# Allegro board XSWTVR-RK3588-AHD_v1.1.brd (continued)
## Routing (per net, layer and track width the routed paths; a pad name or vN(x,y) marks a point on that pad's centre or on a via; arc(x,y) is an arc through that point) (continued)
PCIE20_2_RXP/SATA30_2_RXP: length 140.1
  TOP w0.127: v1(107,100.68) 107.23,100.45 108.78,100.45 109.17,100.84 U1.186
  L3 w0.127: v1(107,100.68) 107.23,100.45 107.51,100.45 107.81,100.14 107.81,62.27 106.1,60.56 95.06,60.56 86.2,51.69 57.59,51.69 56.44,52.85 53.87,52.85 53.56,53.15 53.56,53.72 53.43,53.85 53.18,53.85 53.05,53.72 53.05,53.15 52.75,52.85 52.24,52.85 51.94,53.15 51.94,53.9 51.81,54.02 51.55,54.02 51.43,53.9 51.43,53.15 51.12,52.85 50.62,52.85 50.31,53.15 50.31,53.9 50.18,54.02 49.93,54.02 49.8,53.9 49.8,53.15 49.5,52.85 48.99,52.85 48.68,53.15 48.68,53.9 48.56,54.02 48.3,54.02 48.18,53.9 48.18,53.15 47.87,52.85 47.36,52.85 47.06,53.15 47.06,53.9 46.93,54.02 46.68,54.02 46.55,53.9 46.55,53.15 46.25,52.85 45.74,52.85 45.43,53.15 45.43,53.9 45.31,54.02 45.05,54.02 44.93,53.9 44.93,53.15 44.62,52.85 44.2,52.85 43.48,52.13 42.83,52.13 32.96,42.25 32.96,41.5 v1(33.18,41.28)
  BOTTOM w0.127: v1(33.18,41.28) 32.96,41.05 32.96,40.53 33.05,40.43 J2.43
PCIE20_2_TXN/SATA30_2_TXN: length 2.8
  TOP w0.127: C85.1 112.73,102.18 112.2,102.18 111.41,102.18 111.06,101.84 U1.187
PCIE20_2_TXP/SATA30_2_TXP: length 2.8
  TOP w0.127: U1.188 111.05,102.84 111.4,102.49 112.21,102.49 112.67,102.48 C86.1
PCIEX1_1_CLKREQN_M1_L: length 81.8
  TOP w0.127: v1(91.54,38.84) 91.54,39.19 92.63,40.29 101.65,40.29 101.89,40.05 J24.13
  L3 w0.127: v1(47.31,44.86) 48.39,43.78 48.39,39.91 52.43,35.86 72.28,35.86 73.91,37.5 84.59,37.5 85.95,38.86 91.44,38.86 91.46,38.84 v1(91.54,38.84)
  BOTTOM w0.127: J2.52 35.3,45.26 37.31,43.25 42.77,43.25 44.19,44.67 R53.1 44.69,44.22 46.67,44.22 v1(47.31,44.86)
PCIEX1_1_PERSTN_M1_L: length 83.9
  TOP w0.127: J24.11 102.89,39.6 101.84,40.64 92.32,40.64 90.89,39.22 90.89,38.51 v1(90.8,38.42)
  L3 w0.127: v1(47.33,44.17) 47.91,43.59 47.91,39.71 52.12,35.51 72.28,35.51 72.33,35.56 72.55,35.56 74.07,37.09 84.71,37.09 86.04,38.42 v1(90.8,38.42)
  BOTTOM w0.127: v1(47.33,44.17) 47.33,43.8 46.69,43.16 44.69,43.16 44.19,43.66 ; 44.19,43.66 43.84,43.66 43.1,42.91 36.99,42.91 34.8,45.09 J2.50 ; 44.19,43.66 R52.1
PCIEX1_1_WAKEN_M1_L: length 88
  TOP w0.127: v1(90.46,39.23) 90.46,39.64 91.83,41.01 102.02,41.01 103.41,39.63 103.41,35.9 103.58,35.72 105.26,35.72 105.39,35.6 J24.6
  L3 w0.127: v1(47.31,45.75) 48.85,44.22 48.85,40.04 52.67,36.21 72.17,36.21 73.79,37.83 84.46,37.83 85.86,39.23 90.46,39.23 v1(90.46,39.23)
  BOTTOM w0.127: R54.1 44.19,45.74 ; 44.19,45.74 44.69,45.23 46.79,45.23 v1(47.31,45.75) ; 44.19,45.74 44.19,45.7 43.56,45.07 43.56,44.56 42.56,43.57 37.66,43.57 35.8,45.42 J2.54
PHY0_CLKOUT125: length 4.1
  TOP w0.127: R155.2 130.42,86.57 130.42,87.51 129.72,88.2 U17.35
PHY0_LED0/CFG_EXT: length 8.7
  TOP w0.127: R158.2 132.98,82.03 R157.1 131.07,82.03 129.65,83.45 129.65,86.58 129.22,87.01 U17.32
PHY0_LED1/CFG_LDO0: length 6.3
  TOP w0.127: U17.33 129.41,87.4 129.91,86.9 129.91,84.04 R161.1
PHY0_LED2/CFG_LDO1: length 8.5
  TOP w0.127: R160.2 132.72,84.54 131.54,84.54 R159.1 130.16,84.79 130.16,87.24 129.59,87.81 U17.34
PHY0_MDI0+: length 18
  TOP w0.127: U17.1 127.58,90.85 127.58,91.35 127.79,91.56 129.03,91.56 129.5,92.03 129.5,92.71 v1(129.72,92.93) ; R137.1 120.02,94.52 120.02,94.22 v1(119.79,93.99)
  BOTTOM w0.127: v1(129.72,92.93) 129.5,93.15 129.5,94.76 128.51,95.75 120.97,95.75 120.02,94.8 120.02,94.22 v1(119.79,93.99)
PHY0_MDI0-: length 17.9
  TOP w0.127: R138.1 120.32,94.52 120.32,94.22 v1(120.55,93.99) ; U17.2 127.27,90.85 127.27,91.47 127.66,91.86 128.9,91.86 129.19,92.15 129.19,92.71 v1(128.97,92.93)
  BOTTOM w0.127: v1(128.97,92.93) 129.2,93.17 129.2,93.42 129.07,93.55 128.91,93.55 128.78,93.68 128.78,93.93 128.91,94.06 129.07,94.06 129.2,94.18 129.2,94.63 128.39,95.44 123.1,95.44 122.98,95.32 122.98,95.24 122.85,95.11 122.6,95.11 122.47,95.24 122.47,95.32 122.34,95.44 121.09,95.44 120.32,94.67 120.32,94.22 v1(120.55,93.99)
PHY0_MDI1+: length 8.6
  TOP w0.127: U17.4 126.38,90.85 126.38,93.83 v1(126.6,94.05) ; v1(123.56,94.03) 123.8,94.27 123.8,94.56 R141.1
  BOTTOM w0.127: v1(126.6,94.05) 126.38,94.28 126.38,94.59 126.06,94.9 124.1,94.9 123.79,94.59 123.79,94.26 v1(123.56,94.03)
PHY0_MDI1-: length 8.5
  TOP w0.127: R142.1 124.1,94.56 124.1,94.24 v1(124.31,94.03) ; U17.5 126.07,90.85 126.07,92.81 125.94,92.94 125.69,92.94 125.56,93.07 125.56,93.32 125.69,93.45 125.94,93.45 126.07,93.57 126.07,93.83 v1(125.84,94.05)
  BOTTOM w0.127: v1(125.84,94.05) 126.07,94.28 126.07,94.46 125.94,94.59 125.45,94.59 125.32,94.47 125.32,94.44 125.2,94.31 124.94,94.31 124.82,94.44 124.82,94.47 124.69,94.59 124.23,94.59 124.09,94.46 124.09,94.24 v1(124.31,94.03)
PHY0_MDI2+: length 9.5
  TOP w0.127: v1(125,93.41) 124.77,93.18 124.77,92.59 125.57,91.79 125.57,90.85 U17.6 ; v1(127.39,94.05) 127.62,94.28 127.62,94.54 R143.1
  BOTTOM w0.127: v1(127.39,94.05) 127.64,93.8 127.64,93.15 127.41,92.93 127.16,92.93 127.03,93.06 127.03,93.16 126.87,93.33 126.69,93.33 126.53,93.16 126.53,93.06 126.4,92.93 126.14,92.93 126.02,93.06 126.02,93.16 125.89,93.29 125.64,93.29 125.51,93.16 125.51,93.06 125.38,92.93 124.9,92.93 124.77,93.06 124.77,93.2 124.98,93.41 v1(125,93.41)
PHY0_MDI2-: length 9.6
  TOP w0.127: R145.1 127.92,94.54 127.92,94.28 v1(128.15,94.05) ; U17.7 125.27,90.85 125.27,91.66 124.47,92.46 124.47,93.18 v1(124.24,93.41)
  BOTTOM w0.127: v1(124.24,93.41) 124.47,93.18 124.47,92.93 124.77,92.62 127.54,92.62 127.94,93.02 127.94,93.84 v1(128.15,94.05)
PHY0_MDI3+: length 17.2
  TOP w0.127: R146.1 131.43,94.54 131.43,94.29 v1(131.2,94.06) ; v1(122.62,92.83) 122.39,92.61 122.39,92.05 122.63,91.81 124.02,91.81 124.37,91.45 124.37,90.86 U17.9
  BOTTOM w0.127: v1(122.62,92.83) 122.36,92.58 122.36,92.32 122.57,92.11 123.3,92.11 123.43,92.24 123.43,92.29 123.55,92.42 123.81,92.42 123.93,92.29 123.93,92.24 124.06,92.11 127.76,92.11 127.99,92.34 128.27,92.34 128.5,92.11 128.78,92.11 129,92.34 129.29,92.34 129.51,92.11 129.79,92.11 130.02,92.34 130.3,92.34 130.53,92.11 130.78,92.11 131.43,92.76 131.43,93.84 v1(131.2,94.06)
PHY0_MDI3-: length 17.3
  TOP w0.127: U17.10 124.07,90.85 124.07,91.33 123.89,91.5 122.5,91.5 122.08,91.92 122.08,92.61 v1(121.86,92.83) ; v1(131.96,94.06) 131.73,94.29 131.73,94.54 R147.1
  BOTTOM w0.127: v1(131.96,94.06) 131.73,93.84 131.73,92.63 130.91,91.81 122.44,91.81 122.06,92.19 122.06,92.63 v1(121.86,92.83)
PHY0_MDI_0+: length 2.4
  TOP w0.127: R137.2 120.02,96.28 120.02,96.88 119.54,97.36 U16.2
PHY0_MDI_0-: length 2.4
  TOP w0.127: U16.3 120.81,97.37 120.33,96.89 120.33,96.28 R138.2
PHY0_MDI_1+: length 2.4
  TOP w0.127: R141.2 123.84,96.27 123.84,96.85 123.35,97.33 U16.5
PHY0_MDI_1-: length 2.4
  TOP w0.127: R142.2 124.14,96.19 124.14,96.89 124.62,97.37 U16.6
PHY0_MDI_2+: length 2.4
  TOP w0.127: U16.8 127.17,97.36 127.66,96.88 127.66,96.29 R143.2
PHY0_MDI_2-: length 2.4
  TOP w0.127: R145.2 127.96,96.21 127.96,96.93 128.44,97.41 U16.9
PHY0_MDI_3+: length 2.4
  TOP w0.127: R146.2 131.46,96.29 131.46,96.88 130.98,97.36 U16.11
PHY0_MDI_3-: length 2.4
  TOP w0.127: U16.12 132.25,97.35 131.77,96.87 131.77,96.21 R147.2
PHY0_RSTN: length 4.8
  TOP w0.127: U17.12 121.92,89.81 121.31,90.42 R177.2 R175.2 120.87,92.37 C278.1
PHY0_RXCLK/PHYAD1: length 5
  TOP w0.127: U17.27 126.42,84.13 R165.1 125.72,83.43 125.72,82.01 R182.1
PHY0_RXD0/RXDLY: length 8.4
  TOP w0.127: R178.1 124.08,79.3 123.63,79.75 123.63,80.99 R168.1 123.63,82 123.63,83.43 R169.2 124.59,84.39 124.94,84.39 125.62,85.07 U17.25
PHY0_RXD1/TXDLY: length 9
  TOP w0.127: U17.24 125.22,85.27 124.66,84.7 123.85,84.7 R171.2 122.57,83.43 122.57,82 R170.1 122.54,80.95 122.54,79.79 123.03,79.3 R179.1
PHY0_RXD2/PLLOFF: length 9.5
  TOP w0.127: U17.23 124.82,85.42 124.38,84.98 123.08,84.98 R174.2 121.49,83.4 121.49,82.02 R173.1 121.5,80.97 121.5,79.78 121.97,79.3 R180.1
PHY0_RXD3/PHYAD0: length 10.1
  TOP w0.127: R181.1 120.92,79.3 120.42,79.8 120.42,80.94 R163.1 120.45,82.01 120.45,83.41 R164.2 122.28,85.24 124.09,85.24 124.42,85.57 U17.22
PHY0_RXDV/PHYAD2: length 5.3
  TOP w0.127: R183.1 124.67,82.01 124.67,83.43 R166.1 126.02,84.79 U17.26
PHY0_XTALIN: length 7.8
  TOP w0.203: Y3.3 134.02,88.62 132.41,88.62 C259.1 131.53,88.53 131.24,88.53 R140.1 130.51,88.61 U17.36
PHY0_XTALOUT: length 6.4
  TOP w0.203: U17.37 130.6,89.01 R148.2 131.25,88.98 131.54,88.98 C258.1 132.35,88.95 132.95,88.95 133.29,89.29 Y3.1
PHY1_CLKOUT125: length 4
  TOP w0.127: U19.35 151.62,88.27 152.45,87.44 152.45,86.64 R198.2
PHY1_LED0/CFG_EXT: length 8.7
  TOP w0.127: U19.32 151.13,87.07 151.67,86.54 151.67,83.57 152.64,82.6 153.45,82.6 R200.1 153.94,82.1 R201.2
PHY1_LED1/CFG_LDO0: length 6.1
  TOP w0.127: R204.1 151.94,84.12 151.94,86.81 151.28,87.47 U19.33
PHY1_LED2/CFG_LDO1: length 8.2
  TOP w0.127: U19.34 151.44,87.87 152.2,87.11 152.2,84.87 R202.1 153.48,84.66 154.59,84.66 R203.2
PHY1_MDI0+: length 18.1
  TOP w0.127: R185.1 141.91,94.56 141.91,94.26 v1(141.68,94.04) ; v1(151.75,93) 151.53,92.78 151.53,92.16 151.11,91.74 149.78,91.74 149.61,91.56 149.61,91.17 149.66,91.12 U19.1
  BOTTOM w0.127: v1(151.75,93) 151.52,93.23 151.52,94.71 150.44,95.79 142.86,95.79 141.91,94.84 141.91,94.26 v1(141.68,94.04)
PHY1_MDI0-: length 18
  TOP w0.127: v1(142.44,94.04) 142.23,94.25 142.23,94.58 R184.1 ; v1(151,93) 151.22,92.78 151.22,92.28 150.98,92.04 149.66,92.04 149.3,91.69 149.3,91.15 149.26,91.11 U19.2
  BOTTOM w0.127: v1(151,93) 151.22,93.22 151.22,94.58 150.32,95.49 145.02,95.49 144.89,95.36 144.89,95.23 144.76,95.11 144.51,95.11 144.38,95.23 144.38,95.36 144.25,95.49 144,95.49 143.87,95.36 143.87,95.23 143.75,95.11 143.49,95.11 143.36,95.23 143.36,95.36 143.24,95.49 142.98,95.49 142.21,94.72 142.21,94.26 v1(142.44,94.04)
PHY1_MDI1+: length 8.7
  TOP w0.127: v1(148.63,94.12) 148.41,93.9 148.41,91.18 148.46,91.13 U19.4 ; R187.1 145.69,94.61 145.69,94.32 v1(145.45,94.08)
  BOTTOM w0.127: v1(145.45,94.08) 145.66,94.29 145.66,94.64 146.07,95.04 147.79,95.04 148.38,94.46 148.38,94.33 148.58,94.12 v1(148.63,94.12)
PHY1_MDI1-: length 8.6
  TOP w0.127: R188.1 145.99,94.61 145.99,94.29 v1(146.2,94.08) ; U19.5 148.06,91.11 148.1,91.15 148.1,92.63 147.98,92.76 147.57,92.76 147.45,92.89 147.45,93.14 147.57,93.27 147.98,93.27 148.1,93.4 148.1,93.9 v1(147.88,94.12)
  BOTTOM w0.127: v1(147.88,94.12) 147.99,94.23 147.99,94.41 147.67,94.74 146.19,94.74 145.97,94.51 145.97,94.32 v1(146.2,94.08)
PHY1_MDI2+: length 9.3
  TOP w0.127: v1(149.28,94.1) 149.51,94.33 149.51,94.59 R189.1 ; U19.6 147.66,91.39 147.61,91.44 147.61,91.88 146.81,92.68 146.81,93.3 v1(147.04,93.54)
  BOTTOM w0.127: v1(149.28,94.1) 149.53,93.85 149.53,93.22 149.4,93.09 148.8,93.09 148.69,93.2 148.69,93.33 148.58,93.44 148.42,93.44 148.31,93.33 148.31,93.2 148.2,93.09 148.04,93.09 147.93,93.2 147.93,93.33 147.82,93.44 147.66,93.44 147.55,93.33 147.55,93.2 147.43,93.09 146.93,93.09 146.8,93.22 146.8,93.3 v1(147.04,93.54)
PHY1_MDI2-: length 9.4
  TOP w0.127: U19.7 147.26,91.39 147.3,91.44 147.3,91.76 146.5,92.56 146.5,93.33 v1(146.29,93.54) ; R190.1 149.81,94.59 149.81,94.33 v1(150.04,94.1)
  BOTTOM w0.127: v1(146.29,93.54) 146.49,93.33 146.49,93.09 146.8,92.78 149.53,92.78 149.83,93.09 149.83,93.9 v1(150.04,94.1)
PHY1_MDI3+: length 16.3
  TOP w0.127: U19.9 146.41,90.92 146.41,91.52 146.05,91.87 144.67,91.87 144.42,92.12 144.42,92.68 v1(144.65,92.9) ; v1(153.09,94.12) 153.32,94.34 153.32,94.59 R191.1
  BOTTOM w0.127: v1(153.09,94.12) 153.31,93.89 153.31,93.28 152.49,92.46 145.86,92.46 145.73,92.58 145.73,92.97 145.61,93.1 145.35,93.1 145.22,92.97 145.22,92.58 145.1,92.46 144.64,92.46 144.51,92.58 144.51,92.76 v1(144.65,92.9)
PHY1_MDI3-: length 16.4
  TOP w0.127: v1(143.89,92.9) 144.12,92.68 144.12,92 144.54,91.57 145.93,91.57 146.1,91.39 146.1,90.92 U19.10 ; R192.1 153.62,94.59 153.62,94.34 v1(153.85,94.12)
  BOTTOM w0.127: v1(143.89,92.9) 144.2,92.59 144.2,92.46 144.51,92.15 152.61,92.15 153.62,93.16 153.62,93.89 v1(153.85,94.12)
PHY1_MDI_0+: length 2.4
  TOP w0.127: R185.2 141.92,96.33 141.92,96.92 141.43,97.4 U18.2
PHY1_MDI_0-: length 2.4
  TOP w0.127: U18.3 142.7,97.4 142.22,96.92 142.22,96.32 R184.2
PHY1_MDI_1+: length 2.4
  TOP w0.127: R187.2 145.73,96.32 145.73,96.89 145.24,97.38 U18.5
PHY1_MDI_1-: length 2.4
  TOP w0.127: U18.6 146.51,97.41 146.03,96.93 146.03,96.25 R188.2
PHY1_MDI_2+: length 2.4
  TOP w0.127: U18.8 149.06,97.38 149.52,96.93 149.52,96.31 R189.2
PHY1_MDI_2-: length 2.4
  TOP w0.127: R190.2 149.82,96.29 149.82,96.91 150.33,97.42 U18.9
PHY1_MDI_3+: length 2.4
  TOP w0.127: U18.11 152.87,97.39 153.34,96.92 153.34,96.32 R191.2
PHY1_MDI_3-: length 2.4
  TOP w0.127: R192.2 153.64,96.28 153.64,96.89 154.14,97.39 U18.12
PHY1_RSTN: length 4.7
  TOP w0.127: C300.1 143.03,92.45 R219.2 R221.2 143.15,90.48 143.76,89.87 U19.12
PHY1_RXCLK/PHYAD1: length 5
  TOP w0.127: R226.1 147.83,82.1 147.83,83.52 R209.1 148.46,84.14 U19.27
PHY1_RXD0/RXDLY: length 8.6
  TOP w0.127: U19.25 147.66,85 147.13,84.48 146.71,84.48 R213.2 145.74,83.52 145.74,82.08 R212.1 145.75,81.08 145.75,79.61 R222.1
PHY1_RXD1/TXDLY: length 9.2
  TOP w0.127: U19.24 147.26,85.18 146.82,84.73 146.6,84.73 145.91,84.73 R215.2 144.66,83.49 144.66,82.11 R214.1 144.68,81.06 144.68,79.63 R223.1
PHY1_RXD2/PLLOFF: length 9.8
  TOP w0.127: U19.23 146.86,85.31 146.54,84.99 145.11,84.99 R218.2 143.61,83.49 143.61,82.11 R217.1 143.63,81.07 143.63,79.62 R224.1
PHY1_RXD3/PHYAD0: length 10.3
  TOP w0.127: R225.1 142.58,79.62 142.58,81.08 R207.1 142.59,82.07 142.59,83.53 R208.2 144.34,85.27 146.27,85.27 146.46,85.47 U19.22
PHY1_RXDV/PHYAD2: length 5.3
  TOP w0.127: U19.26 148.06,84.79 R210.1 146.76,83.5 146.76,82.12 R227.1
PHY1_XTALIN: length 7.8
  TOP w0.203: U19.36 152.54,88.67 R186.1 153.26,88.59 153.6,88.59 153.96,88.23 C284.1 154.44,88.68 156.07,88.68 Y4.3
PHY1_XTALOUT: length 6.4
  TOP w0.203: U19.37 152.63,89.07 R193.2 153.28,89.05 153.57,89.05 C283.1 154.39,89.02 155,89.02 155.33,89.35 Y4.1
POWER_EN: length 88
  TOP w0.127: U8.21 106.17,31.08 107.62,32.52 112.92,32.52 v1(113.18,32.26)
  TOP w0.203: U2.3 146.37,70.89 v1(147.12,71.65) R6.2
  BOTTOM w0.127: v1(147.12,71.65) 147.12,72.43 145.54,74.01 131.64,74.01 127.96,70.32 114.08,70.32 113.67,69.91 113.67,62.93 113.18,62.43 113.18,32.78 113.18,32.78 v1(113.18,32.26)
RESET_L: length 98.9
  TOP w0.127: v1(30.35,123.95) ED28.1 29.78,124.8 28.85,125.74 28.85,129.75 U24.J2 ; v1(40.56,62.65) 40.56,50.3 41.97,48.88 R2.2
  BOTTOM w0.127: v1(30.35,123.95) 30.35,123.55 33.36,120.55 39.11,120.55 41.91,117.75 41.91,95.73 45.27,92.37 45.27,67.37 v1(40.56,62.65)
RFFE_VIO_1V8: length 26.9
  BOTTOM w0.127: R344.1 26.7,31.8 C376.1 25.81,32.81 25.81,37.67 26.63,38.49 26.63,41.05 27.52,41.94 37.7,41.94 38.55,41.09 J2.65 ; R344.1 26.24,30.84 26.24,30.84 R51.2 ; R344.1 26.69,30.83 R68.1
RM500U_RESET: length 21.3
  BOTTOM w0.127: Q1.3 24.25,36.86 C84.2 26.19,38.8 26.19,41.2 27.29,42.3 37.94,42.3 39.05,41.19 J2.67
RS232_RXD: length 168.9
  TOP w0.127: v1(18.45,123.93) ED21.1 17.83,125.17 17.28,125.72 17.28,135.62 U24.M3 ; R307.2 89.75,17.48 89.91,17.65 90.24,17.65 v1(90.3,17.71)
  BOTTOM w0.127: v1(18.45,123.93) 19.29,123.09 19.29,121.69 35,105.98 35,105.98 36.31,104.67 36.31,62.88 44.24,54.95 51.94,54.95 59.49,47.41 59.49,29.55 62.73,26.31 62.73,24.28 65.94,21.07 85.22,21.07 88.58,17.71 v1(90.3,17.71)
RS232_TXD: length 171.7
  TOP w0.127: v1(90.27,18.37) 90.26,18.37 90.07,18.18 R306.2 ; v1(19.66,123.93) ED22.1 19.09,125.17 17.93,126.34 17.93,137.77 15.62,140.08 U24.M4
  BOTTOM w0.127: v1(19.66,123.93) 20.16,123.42 20.16,121.3 36.7,104.76 36.7,62.93 44.37,55.26 52.14,55.26 59.83,47.56 59.83,29.77 63.07,26.53 63.07,24.46 66.16,21.38 85.45,21.38 88.46,18.37 v1(90.27,18.37)
RSET0: length 3.5
  TOP w0.127: U17.39 129.01,89.81 R162.1
RSET1: length 3.4
  TOP w0.127: R205.1 151.07,89.87 U19.39
RTC_IN: length 6
  TOP w0.203: U8.3 111.44,21.03 111.66,20.81 111.66,20.05 112.13,19.58 112.41,19.58 C60.1 114.13,19.08 X1.1
RTC_OUT: length 6
  TOP w0.203: U8.4 111.53,21.53 112.03,21.03 112.03,20.24 112.23,20.04 112.53,20.04 C61.1 114.13,20.41 X1.2
RUN_LED: length 197.4
  TOP w0.127: v1(92.48,26.11) 94.32,26.11 95.01,25.41 95.01,23.57 97.05,21.53 U8.45 ; 55.95,109.56 54.27,109.56 v1(53.88,109.18)
  TOP w0.203: D41.4 60.3,152.67 57.66,150.02 57.66,125.85 58.01,125.49 58.01,116.96 58.17,116.8 58.17,111.79 55.95,109.56
  BOTTOM w0.127: v1(53.88,109.18) 51.57,106.86 49.88,106.86 48.91,105.9 48.91,61.12 49.37,60.66 56.38,60.66 58.28,58.76 71.21,58.76 72.72,57.24 72.72,42.41 73.42,41.71 76.13,41.71 76.32,41.52 97.36,41.52 100.67,38.21 100.67,35.62 98.94,33.89 96.36,33.89 92.48,30.02 v1(92.48,26.11)
SARADC_VIN1_KEY/RECOVERY: length 11
  TOP w0.127: U1.1 44.1,106.84 40.74,103.48 37.4,103.48 R1.1 36.81,102.93 ED1.2
SATA0_RXN: length 4.4
  BOTTOM w0.127: U21.43 151.23,56.55 151.22,56.53 151.86,56.53 151.96,56.44 152.68,56.44 152.98,56.74 154.52,56.74 154.71,56.93 154.91,56.93 C357.2
SATA0_RXP: length 4.3
  BOTTOM w0.127: C358.2 154.84,56.63 154.65,56.43 153.1,56.43 152.8,56.13 151.95,56.13 151.85,56.03 151.22,56.03 151.23,56.05 U21.41
SATA0_TXN: length 2.3
  BOTTOM w0.127: C355.2 153.34,57.63 151.99,57.63 151.89,57.53 151.23,57.53 U21.47
SATA0_TXP: length 2.4
  BOTTOM w0.127: U21.49 151.23,58.03 151.92,58.03 152.02,57.94 153.3,57.94 C356.2
SCL_CODEC: length 21.7
  TOP w0.127: R265.1 v1(53.87,117.87) ; v1(57.22,116.39) 57.55,116.06 57.55,112.04 55.62,110.11 48.46,110.11 47.31,108.95 U1.255
  BOTTOM w0.127: v1(57.22,116.39) 55.75,117.87 v1(53.87,117.87)
SD_CLK: length 56.7
  TOP w0.127: R128.1 v1(60.3,138.96) ; U1.11 v1(46.61,96.84)
  L3 w0.127: v1(60.3,138.96) 58.33,136.99 58.33,124.01 59.85,122.5 59.85,121.74 v1(59.25,121.14)
  BOTTOM w0.127: v1(59.25,121.14) 59.99,121.14 61.26,119.87 61.26,113.15 57.95,109.84 51.97,109.84 48.61,106.48 48.61,98.83 v1(46.61,96.84)
SDA_CODEC: length 21
  TOP w0.127: U1.256 46.31,107.93 46.31,108.56 48.1,110.36 49.71,110.36 49.71,110.36 55.42,110.36 57.28,112.22 57.28,115.46 v1(56.94,115.79) ; R266.1 v1(53.87,116.88)
  BOTTOM w0.127: v1(56.94,115.79) 56.89,115.79 55.8,116.88 v1(53.87,116.88)
SDMMC0_CMD: length 56.2
  TOP w0.127: U1.10 v1(46.6,97.84) ; R127.1 v1(60.29,139.99)
  L3 w0.127: v1(60.29,139.99) 57.71,137.41 57.71,123.7 v1(59.24,122.17)
  BOTTOM w0.127: v1(46.6,97.84) 48.07,99.31 48.07,106.83 51.57,110.33 57.52,110.33 60.7,113.51 60.7,119.22 59.22,120.7 59.09,120.7 58.85,120.93 58.85,121.78 v1(59.24,122.17)
SDMMC0_D0: length 55.4
  TOP w0.127: v1(46.57,101.84) 46.45,101.84 U1.6 ; R123.1 v1(60.32,135.84)
  L3 w0.127: v1(59.24,118.03) 59.6,118.03 61.71,120.14 61.71,123.22 60.59,124.35 60.59,124.6 60.46,124.73 60.14,124.73 60.01,124.85 60.01,125.11 60.14,125.24 60.46,125.24 60.59,125.36 60.59,125.62 60.46,125.74 60.14,125.74 60.01,125.87 60.01,126.12 60.14,126.25 60.46,126.25 60.59,126.38 60.59,126.63 60.46,126.76 60.14,126.76 60.01,126.89 60.01,127.14 60.14,127.27 60.46,127.27 60.59,127.39 60.59,127.65 60.46,127.78 60.14,127.78 60.01,127.9 60.01,128.16 60.14,128.28 60.46,128.28 60.59,128.41 60.59,128.66 60.46,128.79 60.14,128.79 60.01,128.92 60.01,129.17 60.14,129.3 60.46,129.3 60.59,129.43 60.59,129.68 60.46,129.81 60.14,129.81 60.01,129.93 60.01,130.19 60.14,130.32 60.46,130.32 60.59,130.44 60.59,131.38 60.46,131.51 60.07,131.51 59.95,131.64 59.95,131.89 60.07,132.02 60.46,132.02 60.59,132.14 60.59,132.4 60.46,132.52 60.07,132.52 59.95,132.65 59.95,132.91 60.07,133.03 60.46,133.03 60.59,133.16 60.59,133.41 59.96,134.04 59.96,135.48 v1(60.32,135.84)
  BOTTOM w0.127: v1(46.57,101.84) 46.21,102.2 46.21,109.04 48.76,111.6 55.41,111.6 55.41,111.61 56.7,111.61 58.74,113.65 58.74,117.54 v1(59.24,118.03)
SDMMC0_D1: length 55.8
  TOP w0.127: U1.7 46.42,100.84 46.46,100.8 v1(46.57,100.8) ; R124.1 v1(60.33,134.81)
  L3 w0.127: v1(60.33,134.81) 61.25,133.89 61.25,129.87 61.38,129.74 61.84,129.74 61.97,129.61 61.97,129.36 61.84,129.23 61.38,129.23 61.25,129.11 61.25,128.85 61.38,128.73 61.84,128.73 61.97,128.6 61.97,128.34 61.84,128.22 61.38,128.22 61.25,128.09 61.25,127.84 61.38,127.71 61.84,127.71 61.97,127.58 61.97,127.33 61.84,127.2 61.38,127.2 61.25,127.07 61.25,126.82 61.38,126.69 61.84,126.69 61.97,126.57 61.97,126.31 61.84,126.19 61.38,126.19 61.25,126.06 61.25,125.8 61.38,125.68 61.84,125.68 61.97,125.55 61.97,125.3 61.84,125.17 61.38,125.17 61.25,125.04 61.25,124.65 62.17,123.73 62.17,119.93 v1(59.24,116.99)
  BOTTOM w0.127: v1(46.57,100.8) 46.7,100.93 46.7,101.36 46.98,101.64 46.98,102.14 46.7,102.42 46.7,102.98 46.97,103.25 46.97,103.49 46.7,103.76 46.7,104 46.97,104.27 46.97,104.51 46.7,104.78 46.7,105.02 46.97,105.29 46.97,105.52 46.56,105.93 46.56,108.66 46.87,108.97 47.05,108.97 47.13,108.88 47.31,108.88 47.49,109.06 47.49,109.24 47.41,109.33 47.41,109.51 47.59,109.69 47.77,109.69 47.85,109.6 48.03,109.6 48.21,109.78 48.21,109.96 48.13,110.05 48.13,110.22 48.31,110.4 48.49,110.4 48.57,110.32 48.75,110.32 48.93,110.5 48.93,110.68 48.84,110.76 48.84,110.94 49.18,111.28 56.88,111.28 59.24,113.64 v1(59.24,116.99)
SDMMC0_D2: length 55.2
  TOP w0.127: U1.8 46.52,99.84 v1(46.57,99.84) ; R125.1 v1(60.32,136.88)
  L3 w0.127: v1(60.32,136.88) 59.6,136.16 59.6,133.73 59.55,133.68 59.55,133.13 59.39,132.97 59.39,132.62 59.54,132.46 59.54,132.11 59.39,131.95 59.39,131.6 59.54,131.45 59.54,131.09 59.39,130.94 59.39,130.58 59.54,130.43 59.54,130.08 59.39,129.92 59.39,129.57 59.54,129.41 59.54,129.06 59.39,128.91 59.39,128.55 59.54,128.4 59.54,128.04 59.39,127.89 59.39,127.54 59.54,127.38 59.54,127.03 59.39,126.87 59.39,126.52 59.54,126.37 59.54,126.01 59.39,125.86 59.39,125.5 59.54,125.35 59.54,124.7 61.06,123.18 61.06,122.93 61.27,122.72 61.27,122.42 61.17,122.31 60.96,122.31 60.86,122.21 60.86,121.91 60.96,121.81 61.17,121.81 61.27,121.7 61.27,121.4 61.06,121.2 61.06,120.89 60.75,120.58 60.75,120.4 60.95,120.2 60.95,120.02 60.77,119.84 60.59,119.84 60.39,120.04 60.21,120.04 60.04,119.86 60.04,119.68 60.23,119.48 60.23,119.3 60.05,119.12 59.88,119.12 59.68,119.32 59.5,119.32 v1(59.24,119.06)
  BOTTOM w0.127: v1(46.57,99.84) 47.35,100.62 47.35,105.97 47.16,106.16 47.08,106.16 46.95,106.29 46.95,106.55 47.08,106.67 47.16,106.67 47.28,106.8 47.28,107.05 47.16,107.18 47.08,107.18 46.95,107.31 46.95,107.56 47.08,107.69 47.16,107.69 47.28,107.82 47.28,108.13 50.1,110.95 57.07,110.95 59.66,113.54 59.66,114.61 59.87,114.83 59.87,115.12 59.66,115.34 59.66,115.63 59.87,115.85 59.87,116.14 59.66,116.35 59.66,116.65 59.87,116.86 59.87,117.15 59.66,117.37 59.66,117.66 59.87,117.88 59.87,118.17 59.66,118.39 59.66,118.64 v1(59.24,119.06)
SDMMC0_D3: length 54.9
  TOP w0.127: U1.9 v1(46.57,98.84) ; R126.1 v1(60.31,137.91)
  L3 w0.127: v1(60.31,137.91) 58.88,136.48 58.88,124.36 60.4,122.84 60.4,121.25 v1(59.24,120.09)
  BOTTOM w0.127: v1(46.57,98.84) 47.74,100 47.74,107.15 48.32,107.73 48.32,107.91 48.1,108.13 48.1,108.31 48.28,108.48 48.46,108.48 48.68,108.27 48.86,108.27 49.04,108.45 49.04,108.63 48.82,108.84 48.82,109.02 49,109.2 49.18,109.2 49.39,108.99 49.57,108.99 49.75,109.16 49.75,109.34 49.54,109.56 49.54,109.74 49.72,109.92 49.89,109.92 50.11,109.7 50.29,109.7 51.23,110.64 57.28,110.64 60.28,113.63 60.28,119.05 v1(59.24,120.09)
SDMMC_CLK: length 11.8
  TOP w0.127: R359.1 21.4,26.12 25.18,22.34 27,22.34 27.75,23.08 U22.18
SDMMC_CMD: length 14.2
  TOP w0.127: R254.1 22.51,23.99 24.81,21.7 27.35,21.7 29.15,23.49 29.15,26.85 28.93,27.07 U22.20
SDMMC_D0: length 5.8
  TOP w0.127: U22.13 22.61,25.91 20.84,27.67 R255.1
SDMMC_D1: length 5.8
  TOP w0.127: U22.12 22.76,26.57 21.55,27.78 21.55,29.19 21.29,29.46 R256.1
SDMMC_D2: length 18.4
  TOP w0.127: R252.1 22.89,21.8 24.18,20.51 27.91,20.51 30.4,23 30.4,28.03 29.86,28.57 U22.23
SDMMC_D3: length 16.4
  TOP w0.127: U22.22 29.24,28.07 29.77,27.54 29.77,23.31 27.59,21.13 24.46,21.13 22.69,22.9 R253.1
SDMMC_DET_L: length 15.9
  TOP w0.127: J22.9 17.46,30.59 D26.1 17.51,30.59 19.04,32.13 22.15,32.13 22.42,31.86 22.42,29.21 24.06,27.57 U22.10
SWCLK: length 9.4
  TOP w0.127: U8.49 100.67,18.84 100.32,19.19 97,19.19 J1.2
SWDIO: length 7.1
  TOP w0.127: J1.3 93.64,24.33 96.93,21.03 U8.46
TYPEC0_OTG_DM: length 25.4
  TOP w0.127: U1.58 44.52,49.84 44.17,50.19 43.34,50.19 41.48,52.04 41.48,64.79 39.83,66.44 34.98,66.44 R228.2
TYPEC0_OTG_DP: length 25.4
  TOP w0.127: R230.2 34.98,66.72 39.95,66.72 41.76,64.9 41.76,52.16 43.45,50.47 44.16,50.47 44.53,50.84 U1.57
TYPEC0_SSRX1N: length 24.2
  TOP w0.127: U1.66 47.31,42.6 46.15,41.44 42.52,41.44 36.42,47.54 36.42,49.37 33.32,52.48 29.97,52.48 R233.1
TYPEC0_SSRX1P: length 24.1
  TOP w0.127: U1.65 46.31,42 46.03,41.72 42.64,41.72 42.36,42 42.36,42.3 42.15,42.51 41.85,42.51 41.64,42.71 41.64,43.01 41.43,43.22 41.13,43.22 40.92,43.43 40.92,43.73 40.71,43.94 40.41,43.94 40.2,44.15 40.2,44.45 39.99,44.66 39.69,44.66 36.7,47.65 36.7,49.49 33.43,52.76 29.99,52.76 R234.1
TYPEC0_SSTX1N: length 28.8
  TOP w0.127: C309.1 29.85,50.09 34.43,50.09 35.19,49.32 35.19,46.67 41.46,40.4 49.82,40.4 50.6,41.17 50.6,41.5 51.31,42.21 U1.70
TYPEC0_SSTX1P: length 28.8
  TOP w0.127: C313.1 29.66,50.54 29.83,50.37 30.86,50.37 30.98,50.49 30.98,50.51 31.11,50.63 31.36,50.63 31.49,50.51 31.49,50.49 31.62,50.37 31.87,50.37 32,50.49 32,50.51 32.13,50.63 32.38,50.63 32.51,50.51 32.51,50.49 32.63,50.37 32.89,50.37 33.01,50.49 33.01,50.51 33.14,50.63 33.4,50.63 33.52,50.51 33.52,50.49 33.65,50.37 34.55,50.37 35.47,49.44 35.47,46.78 41.58,40.68 49.71,40.68 50.31,41.28 U1.69
TYPEC0_USB20_OTG_ID: length 16.2
  TOP w0.127: SW3.2 56.78,117.31 57.29,116.79 57.55,116.79 57.81,116.53 57.81,111.91 55.72,109.82 50.96,109.82 50.31,109.17 U1.252
TYPEC0_USB20_VBUSDET: length 21.8
  TOP w0.127: R236.2 R238.1 C314.1 39.91,62.1 39.91,59.25 39.56,58.91 39.56,49.77 41.49,47.84 U1.60
UART1_RX_M1: length 81.7
  TOP w0.127: U1.240 v1(62.31,109.15)
  L3 w0.127: v1(62.31,109.15) 61.81,108.65 61.24,108.08 56.56,108.08 54.79,109.84 50.79,109.84 41.33,100.38 41.33,57.26 38.3,54.23 v1(38.3,51.45)
  BOTTOM w0.127: J2.64 v1(38.3,51.45)
UART1_TX_M1: length 81.2
  TOP w0.127: U1.241 v1(61.31,109.15)
  L3 w0.127: v1(37.8,51.69) 37.8,54.36 40.89,57.44 40.89,100.45 50.58,110.15 55,110.15 56.75,108.39 60.56,108.39 v1(61.31,109.15)
  BOTTOM w0.127: J2.62 v1(37.8,51.69)
UART2_RX_M0_DEBUG: length 135.6
  TOP w0.127: U25.12 v1(87.93,15.64) ; U1.3 43.92,104.84 43.04,103.96 43.04,99.26 41.38,97.6 v1(35.77,97.6)
  BOTTOM w0.127: v1(87.93,15.64) 83.76,19.81 65.15,19.81 61.2,23.76 61.2,27.29 59.15,29.34 59.15,47.19 51.71,54.63 44.09,54.63 35.92,62.8 35.92,97.08 35.77,97.23 v1(35.77,97.6)
UART2_TX_M0_DEBUG: length 140
  TOP w0.127: v1(88.72,15.61) 87.47,14.37 U25.11 ; U1.2 43.97,105.84 42.56,104.42 42.56,99.53 41.23,98.2 v1(35.12,98.2)
  BOTTOM w0.127: v1(35.12,98.2) 35.12,86.13 35.54,85.71 35.54,62.73 43.97,54.29 51.47,54.29 58.82,46.95 58.82,29.18 60.91,27.09 60.91,23.53 64.94,19.5 83.52,19.5 87.76,15.26 88.37,15.26 v1(88.72,15.61)
UART3_RX_M0: length 110.3
  TOP w0.127: v1(106.35,111.02) 106.09,110.76 98.86,110.76 90.07,119.54 U15.20 ; J24.5 105.89,39.11 105.88,39.12 v1(105.88,39.49)
  L3 w0.127: v1(107.42,103.93) 107.42,104.02 107.24,104.19 107.24,110.13 v1(106.35,111.02)
  BOTTOM w0.127: v1(107.42,103.93) 107.42,63.32 110.12,60.62 110.12,41.78 108.08,39.75 106.14,39.75 v1(105.88,39.49)
UART3_TX_M0: length 112.9
  TOP w0.127: v1(106.38,39.19) 106.38,38.82 106.39,38.81 J24.4 ; v1(105.73,111.13) 98.98,111.13 90.49,119.62 90.49,129.35 91.17,130.03 U15.21
  L3 w0.127: v1(107.63,104.55) 107.63,110.34 106.58,111.39 105.99,111.39 v1(105.73,111.13)
  BOTTOM w0.127: v1(106.38,39.19) 108.14,39.19 110.52,41.57 110.52,60.81 107.84,63.49 107.84,104.34 v1(107.63,104.55)
UART6_CTSN_M1: length 37.8
  TOP w0.127: U14.42 v1(77.78,136.92) ; U1.230 v1(72.31,109.15)
  L3 w0.127: v1(72.31,109.15) 72.31,110.41 77.39,115.48 77.39,131.2 79.06,132.88 79.06,137.49 78.13,138.42 77.42,138.42 77.11,138.11 77.11,137.59 v1(77.78,136.92)
UART6_RTSN_M1: length 35.2
  TOP w0.127: U14.43 v1(77.78,137.82) ; v1(70.67,109.26) 70.31,108.9 U1.232
  L3 w0.127: v1(77.78,137.82) 78.58,137.02 78.58,132.99 76.97,131.38 76.97,115.56 v1(70.67,109.26)
UART6_RX_M1: length 35
  TOP w0.127: U14.40 v1(77.75,135.12) ; U1.235 v1(67.31,109.15)
  L3 w0.127: v1(67.31,109.15) 67.31,109.1 67.66,108.75 68.52,108.75 76,116.24 76,134.49 76.63,135.12 v1(77.75,135.12)
UART6_TX_M1: length 34
  TOP w0.127: U1.234 v1(68.31,109.15) ; U14.41 v1(77.76,136.02)
  L3 w0.127: v1(68.31,109.15) 75.61,116.45 75.61,134.7 76.93,136.02 v1(77.76,136.02)
UART7_RX_M1: length 141.9
  TOP w0.127: v1(99.31,114.4) 99.68,114.77 110.22,114.77 116.58,108.41 116.58,94.76 117.1,94.25 v1(117.55,94.25) ; U24.A2 46.42,132.18 46.42,126.6 48.17,124.85 ED50.1 48.77,123.97 v1(48.78,123.97) ; v1(109.06,69.84) 109.24,69.84 U1.155
  BOTTOM w0.127: v1(117.55,94.25) 117.55,87.25 116.5,86.2 114.43,86.2 113.41,87.22 111.45,87.22 111.08,86.85 111.08,81.39 113.22,79.25 113.22,76.89 109.06,72.72 v1(109.06,69.84) ; v1(48.78,123.97) 50.11,125.3 61.53,125.3 63.66,123.18 63.66,115.44 65.12,113.98 98.89,113.98 v1(99.31,114.4)
UART7_TX_M1: length 138.8
  TOP w0.127: v1(47.54,123.97) 47.53,123.97 ED49.1 46.93,124.77 45.32,126.39 U24.A1 ; U1.154 109.13,68.84 v1(109.06,68.84) ; v1(117.12,93.73) 116.2,94.65 116.2,108.25 110.07,114.38 v1(99.88,114.38)
  BOTTOM w0.127: v1(117.12,93.73) 117.12,87.45 116.28,86.61 114.58,86.61 113.59,87.6 111.32,87.6 110.75,87.03 110.75,81.27 112.03,79.99 112.85,79.18 112.85,77.01 108.69,72.85 108.69,69.2 v1(109.06,68.84) ; v1(47.54,123.97) 49.24,125.67 61.68,125.67 64.02,123.33 64.02,115.71 65.43,114.3 98.64,114.3 99.13,114.78 99.48,114.78 v1(99.88,114.38)
UART9_RX_M1: length 29.4
  TOP w0.127: J24.16 100.39,33.14 100.83,32.7 106.77,32.7 107.21,33.14 116.95,33.14 117.52,32.57 117.52,31.06 114.8,28.34 112.3,28.34 111.49,27.53 U8.16
UART9_TX_M1: length 26.5
  TOP w0.127: J24.17 99.89,36.04 99.88,36.03 99.88,33.11 100.15,32.84 100.16,32.84 100.65,32.34 106.92,32.34 107.41,32.84 113.58,32.84 114.11,32.31 114.11,31.34 113.86,31.09 113.21,31.09 111.78,29.66 108.3,29.66 U8.17
USB20_HOST0_DM: length 18.8
  TOP w0.127: U1.42 44.63,65.84 44.27,66.2 43.3,66.2 40.62,68.87 40.44,68.87 40.43,68.86 40.25,68.86 40.07,69.04 40.07,69.22 40.09,69.23 40.09,69.41 39.91,69.59 39.73,69.59 39.71,69.58 39.53,69.58 39.35,69.76 39.35,69.94 39.37,69.95 39.37,70.13 39.19,70.31 39.01,70.31 39,70.3 38.82,70.3 38.64,70.48 38.64,70.66 38.65,70.67 38.65,70.85 38.47,71.03 38.29,71.03 38.28,71.02 38.1,71.02 37.92,71.19 37.92,71.37 37.93,71.39 37.93,71.57 37.75,71.75 37.57,71.75 37.56,71.73 37.38,71.73 37.2,71.91 37.2,72.09 37.21,72.11 37.21,72.28 37.03,72.46 36.85,72.46 36.84,72.45 36.66,72.45 36.48,72.63 36.48,72.81 36.49,72.82 36.49,73 36.31,73.18 36.13,73.18 36.12,73.17 35.94,73.17 35.76,73.35 35.76,73.53 35.77,73.54 35.77,73.72 35.6,73.9 35.42,73.9 35.4,73.89 35.22,73.89 35.04,74.07 35.04,74.25 35.06,74.26 35.06,74.44 34.88,74.62 34.7,74.62 34.68,74.61 34.51,74.61 34.33,74.79 34.33,74.97 34.34,74.98 34.34,75.16 33.41,76.08 U28.7
USB20_HOST0_DP: length 18.8
  TOP w0.127: v1(34.01,76.01) 34.01,75.88 34.06,75.84 43.42,66.48 44.22,66.48 44.58,66.84 U1.41 ; U28.1 v1(33.41,78.43)
  BOTTOM w0.127: v1(34.01,76.01) 33.41,76.6 v1(33.41,78.43)
USB20_HOST1_DM: length 45.9
  TOP w0.127: U22.3 26.75,29.96 26.63,30.07 26.63,37.57 34.16,45.09 34.16,48.52 v1(34.38,48.74) ; v1(43.56,53.26) 43.35,53.48 43.35,56.92 43.49,57.07 43.49,57.43 43.35,57.57 43.35,57.94 43.49,58.08 43.49,58.45 43.35,58.59 43.35,58.96 43.49,59.1 43.49,59.46 43.35,59.61 43.35,59.97 43.49,60.11 43.49,60.48 43.35,60.62 43.35,61.78 43.77,62.2 44.22,62.2 44.58,61.84 U1.46
  BOTTOM w0.127: v1(43.56,53.26) 43.34,53.04 43.34,52.66 42.98,52.29 36.5,52.29 34.16,49.95 34.16,48.97 v1(34.38,48.74)
USB20_HOST1_DP: length 45.9
  TOP w0.127: U22.4 26.25,29.97 26.36,30.08 26.36,37.68 33.88,45.21 33.88,48.52 v1(33.65,48.74) ; v1(42.83,53.26) 43.07,53.5 43.07,61.89 43.65,62.48 44.26,62.48 44.62,62.84 U1.45
  BOTTOM w0.127: v1(33.65,48.74) 33.88,48.97 33.88,50.06 36.39,52.57 42.86,52.57 43.06,52.77 43.06,53.04 v1(42.83,53.26)
USB30_HOST0_SSRXN: length 19.6
  TOP w0.127: R233.2 28.75,52.5 27.89,52.5 27.34,51.95 ED12.1 26.83,52.44 26.42,52.44 v1(26.18,52.21)
  BOTTOM w0.127: J20.5 13.74,56.78 13.86,56.65 13.86,55.17 14.78,54.25 19.95,54.25 21.76,52.44 25.95,52.44 v1(26.18,52.21)
USB30_HOST0_SSRXP: length 19.6
  TOP w0.127: R234.2 28.76,52.78 27.88,52.78 27.34,53.32 ED11.1 26.73,52.72 26.4,52.72 v1(26.18,52.94)
  BOTTOM w0.127: v1(26.18,52.94) 25.96,52.72 25.71,52.72 25.52,52.91 25.2,52.91 25.01,52.72 24.69,52.72 24.5,52.91 24.18,52.91 23.99,52.72 23.68,52.72 23.49,52.91 23.17,52.91 22.98,52.72 21.88,52.72 20.06,54.53 14.9,54.53 14.14,55.29 14.14,56.65 14.27,56.78 J20.6
USB30_HOST0_SSTXN: length 15.3
  TOP w0.127: J20.8 19.86,55.91 19.86,52.68 22.41,50.13 26.79,50.13 ED10.1 27.29,49.66 27.74,50.12 28.87,50.12 C309.2
USB30_HOST0_SSTXP: length 15.3
  TOP w0.127: J20.9 20.14,55.91 20.14,52.79 22.53,50.41 23.74,50.41 23.94,50.6 24.25,50.6 24.44,50.41 24.76,50.41 24.95,50.6 25.27,50.6 25.46,50.41 25.78,50.41 25.97,50.6 26.28,50.6 26.48,50.41 26.86,50.41 ED9.1 27.34,50.84 27.79,50.39 28.92,50.39 C313.2
USB30_OTG0_DM: length 20.1
  TOP w0.127: J20.2 17.15,59.43 17.15,60.23 23.37,66.46 25.66,66.46 25.86,66.25 26.16,66.25 26.37,66.46 26.67,66.46 26.88,66.25 27.18,66.25 27.39,66.46 27.69,66.46 27.89,66.25 28.2,66.25 28.4,66.46 29.03,66.46 ED13.1 29.59,65.93 30.12,66.45 30.86,66.45 R229.1
USB30_OTG0_DP: length 20.1
  TOP w0.127: J20.3 16.03,58.57 16.87,59.41 16.87,60.35 23.25,66.74 29.03,66.74 ED14.1 29.59,67.27 30.1,66.76 30.88,66.76 R231.1
USB_HOST_PWREN_H: length 70.5
  TOP w0.127: v1(38.88,53.76) 37,55.64 U20.4 ; U1.249 v1(53.31,109.17)
  L3 w0.127: v1(53.31,109.17) 52.94,109.54 51.03,109.54 41.77,100.28 41.77,57.01 38.88,54.13 v1(38.88,53.76)
USIM1_CLK: length 17.4
  TOP w0.127: v1(30.3,46.21) 27.43,43.33 22.14,43.33 C100.1 20.93,43.38 20.02,43.38 19.43,42.79 D7.1 19.42,42.75 16.06,42.75 arc(16.02,42.75) J4.C3
  BOTTOM w0.127: J2.32 v1(30.3,46.21)
USIM1_DATA: length 20.9
  TOP w0.127: 23.1,43.94 23.09,43.95 R59.2 23.09,45.45 22.93,45.6 22.93,46.13 23.23,46.43 28.87,46.43 v1(30.8,48.37) ; 23.1,43.94 21.29,43.94 20.61,44.62 19.99,44.62 19.44,44.06 D10.1 19.43,44.02 16.06,44.02 arc(16.02,44.02) J4.C7 ; 23.1,43.94 24.06,43.94 C99.1
  BOTTOM w0.127: J2.34 30.8,48.37 v1(30.8,48.37)
USIM1_RST: length 17.1
  TOP w0.127: v1(29.8,48.37) 28.58,47.14 19.82,47.14 19.45,46.77 C98.1 19.45,46.34 D8.1 19.44,45.29 16.06,45.29 arc(16.02,45.29) J4.C2
  BOTTOM w0.127: v1(29.8,48.37) 29.8,48.37 J2.30
USIM1_VDD: length 27.6
  TOP w0.203: R59.1 26.31,44.96 v2(26.57,45.22)
  TOP w0.381: v2(19.46,50.84) C97.1 C96.1 D9.1 16.06,47.83 J4.C1
  BOTTOM w0.381: v2(19.46,50.84) 25.36,50.84 26.13,50.08 26.13,45.66 v2(26.57,45.22) 27.19,45.22 27.19,45.22 30.75,45.22 31.3,45.77 J2.36
V_ANT: length 3.1
  TOP w0.305: L5.2 83.46,145.38 83.77,145.08 U15.9
V_DDA: length 13.8
  TOP w0.254: U8.13 112.14,26.03 C65.1 v2(113.7,26.77)
  TOP w0.305: F1.2 110.46,30.28 C74.1 C73.1 112.22,30.89 112.78,31.45 v2(112.78,31.7)
  TOP w0.508: v2(112.78,31.7) v2(113.5,31.7)
  BOTTOM w0.508: v2(113.7,26.77) 112.78,27.7 v2(112.78,31.7) v2(113.5,31.7)
VIDEO_IND: length 15.6
  TOP w0.127: J24.10 103.38,34.52 103.38,33.56 103.5,33.44 110.65,33.44 111.31,34.09 R102.1
WAKEUP_RK3588: length 213.8
  TOP w0.127: v1(98.34,32.44) 98.6,32.18 98.6,31.83 98.99,31.43 Q33.3 ; v1(43.57,92.36) 40.33,92.36 v1(34.04,86.08) ; v1(50.13,106.24) 49.77,106.24 49.76,106.24 48.75,106.24 48.31,106.68 U1.254 ; v1(34.01,98.14) 32.77,99.39 14.89,99.39 13.79,100.48 13.79,103.12 13.22,103.7 R347.2
  L3 w0.127: v1(34.01,98.14) 34.85,97.3 34.85,86.88 v1(34.04,86.08) ; v1(98.34,32.44) 96.51,30.61 87.58,30.61 85.11,28.14 73.78,28.14 72.51,29.41 66.71,29.41 66.56,29.56 36.97,29.56 36.36,30.18 31.42,30.18 28.9,32.7 28.9,39.98 43.57,54.66 v1(43.57,92.36) 43.57,100.17 49.64,106.24 v1(50.13,106.24)
WIFI1T1R_CLK: length 1.8
  TOP w0.127: R128.2 62.22,138.72 U14.18
WIFI1T1R_CMD: length 1.8
  TOP w0.127: U14.17 62.34,139.62 R127.2
WIFI1T1R_D0: length 1.8
  TOP w0.127: U14.21 62.16,136.02 R123.2
WIFI1T1R_D1: length 1.8
  TOP w0.127: U14.22 62.29,135.12 R124.2
WIFI1T1R_D2: length 1.7
  TOP w0.127: R125.2 62.63,136.88 62.68,136.92 U14.20
WIFI1T1R_D3: length 1.7
  TOP w0.127: R126.2 62.58,137.91 62.66,137.82 U14.19
WIFI_3V3: length 6.6
  TOP w0.508: R130.2 74.43,124.82 D23.1 74.75,125.91 C247.1 74.47,126.95 C249.1 74.45,127.69 C250.1 74.45,128.5 C248.1 74.49,129.34 U14.36
WIFI_ANT: length 7.5
  TOP w0.559: R131.1 69.91,155.39 C252.1 70.02,156.29 70.42,156.68 75.65,156.68 J18.3
WIFI_ANT0: length 9.7
  TOP w0.559: U14.9 67.29,146.75 arc(67.34,146.99) 67.48,147.2 69.05,148.76 arc(69.69,149.73) 69.92,150.87 C251.1 R131.2
WIFI_ANT1: length 6.4
  TOP w0.559: U14.2 73.59,146.84 73.02,147.42 arc(72.81,147.73) 72.74,148.09 72.74,149.01 arc(72.96,149.55) 73.5,149.77 C253.1 74.19,149.78 R132.2
WIFI_REG_ON: length 59.2
  TOP w0.127: v1(78.29,143.51) 79.27,142.52 79.27,115.1 80.58,113.79 83.5,113.79 87.31,109.98 U1.215 ; U14.15 v1(62.35,141.42)
  L3 w0.127: v1(78.29,143.51) 76.2,141.42 v1(62.35,141.42)
WIFI_WAKE_HOST: length 41.9
  TOP w0.127: U14.16 62.75,140.52 62.49,140.79 59.63,140.79 59.02,140.18 59.02,133.98 62.05,130.95 62.05,129.12 61.63,128.7 60.61,128.7 60.61,128.7 59.99,128.7 59.51,128.23 59.51,127.6 58.82,126.91 58.82,111.49 56.31,108.98 U1.246
XO: length 4.8
  TOP w0.203: R84.2 121.31,36.55 R83.1 121.56,36.81 123.15,36.81 123.56,36.4 U11.95
XO1: length 4.8
  TOP w0.203: R103.2 36.86,36.41 R101.1 37.11,36.67 38.7,36.67 39.11,36.26 U13.95
N16931377: length 3.1
  BOTTOM w0.127: Q18.3 83.92,38.1 84.85,37.17 84.9,37.17 ; 84.9,37.17 Q14.1 ; 84.9,37.17 84.77,37.04 R274.2
N16931417: length 2.4
  BOTTOM w0.127: R280.2 79.74,37.21 R282.1 79.82,37.15 Q18.1
N16931861: length 3.3
  BOTTOM w0.127: R275.2 73.47,36.69 Q15.1 73.1,37.33 72.19,38.23 Q19.3
N16931902: length 2.5
  BOTTOM w0.127: R278.2 67.91,37.33 R283.1 69.38,37.27 Q19.1
N16962772: length 39.7
  TOP w0.203: C119.2 104.61,11.43 105.46,10.59 111.59,10.59 113.93,12.93 124.28,12.93 125.72,14.38 125.72,16.53 126.69,17.49 126.69,17.49 127.56,18.35 U11.12
N16962795: length 40.6
  TOP w0.203: U11.13 127.94,19.6 127.94,18.19 126.15,16.41 126.15,14.2 124.47,12.52 114.1,12.52 111.76,10.18 105.29,10.18 104.44,11.02 94.46,11.02 94.07,10.63 C120.2
N16962816: length 18.6
  TOP w0.203: U11.18 129.96,17.87 129.44,17.35 129.44,13.84 126.48,10.88 119.16,10.88 118.75,11.29 C111.2
N16962837: length 19.1
  TOP w0.203: U11.19 130.36,18.64 130.34,18.62 130.34,17.66 129.84,17.17 129.84,13.64 126.7,10.49 C121.2
N16962856: length 7
  TOP w0.203: C122.2 133.37,13.3 133.37,16.9 132.34,17.92 132.34,18.85 132.36,18.87 U11.24
N16962873: length 7
  TOP w0.203: C123.2 133.75,13.4 133.75,17.05 132.72,18.08 132.72,18.7 132.76,18.73 U11.25
N16962896: length 13.8
  TOP w0.203: C124.2 142.14,9.81 139.18,12.77 139.18,14.3 134.76,18.72 U11.30
N16962917: length 13.2
  TOP w0.203: U11.31 135.16,18.88 139.57,14.46 139.57,12.93 142.19,10.31 142.79,10.31 C112.2
N16962947: length 6.6
  TOP w0.127: C113.2 123.17,15.17 C114.1 123.17,16.63 124.27,17.74 125.59,17.74 126.36,18.51 U11.9
N16962991: length 6.4
  TOP w0.127: C127.2 124.07,16.15 C114.2 124.07,17.13 124.42,17.49 125.69,17.49 126.76,18.55 U11.10
N16963001: length 5.2
  TOP w0.127: U11.15 128.76,18.08 127.21,16.54 C115.1 127.19,16.16 C126.2
N16963037: length 4.9
  TOP w0.127: C116.2 128.14,16.15 C115.2 128.11,17.05 129.12,18.06 129.12,19.58 U11.16
N16963051: length 4.5
  TOP w0.127: U11.21 C118.1 131.12,16.2 C117.2
N16963101: length 4.7
  TOP w0.127: C129.2 132.08,16.21 C118.2 131.56,16.73 U11.22
N16963115: length 5.2
  TOP w0.203: C128.2 135.11,16.25 C130.1 135.26,16.4 135.26,16.86 133.59,18.53 133.59,19.44 133.57,19.46 133.57,19.6 U11.27
N16963147: length 5.3
  TOP w0.203: U11.28 133.97,19.6 133.97,18.69 135.78,16.88 135.78,16.53 C130.2 136.06,16.25 C133.2
N16963702: length 4.5
  TOP w0.203: R85.2 121.65,37.24 123.23,37.24 123.96,36.52 U11.94
N16963854: length 3.1
  TOP w0.127: U11.45 139.42,25.96 R86.2
N16963899: length 3
  TOP w0.127: U11.46 139.51,26.36 R87.2
N16974815: length 3
  TOP w0.203: FB9.2 114.17,35.76 C125.1 115.56,35.15 Y1.4
N16974853: length 2.5
  TOP w0.203: Y1.1 118.38,35.55 C131.1 119.29,35.55 R84.1
N16985810: length 3.3
  BOTTOM w0.127: Q20.3 83.92,33.67 84.81,32.77 Q16.1 85.25,32.13 R276.2
N16985852: length 2.4
  BOTTOM w0.127: Q20.1 79.83,32.72 R284.1 79.75,32.77 R279.2
N17187928: length 1.8
  TOP w0.254: U20.3 34.4,58.12 35.13,57.4 R235.1
N17430388: length 7.2
  TOP w0.203: 31.56,104.74 31.96,104.34 C14.1
N17430409: length 33.7
  TOP w0.508: R9.2 v1(33.17,112.37)
  L3 w0.508: v1(3.15,106.71) 9.72,106.71 16.04,113.04 32.81,113.04 33.17,112.68 v1(33.17,112.37)
N17430604: length 1.8
  TOP w0.203: U3.1 38.58,105.25 C14.2
N17430621: length 1
  TOP w0.203: R12.2 34.16,111.72 R9.1
N17430780: length 6.4
  TOP w0.203: R16.2 36.18,111.7 R13.1 36.18,110.39 36.66,109.91 37.73,109.91 37.98,109.66 37.98,108.01 37.76,107.79 U3.3
N17430784: length 5.1
  TOP w0.203: U3.6 31.37,107.79 30.84,107.79 29.94,108.69 29.94,110.4 R15.2 29.52,110.81 C28.1
N17430790: length 3.3
  TOP w0.203: U3.5 31.84,109.06 32.11,109.33 R18.2 33.15,110.74 R12.1
N17430830: length 2.6
  TOP w0.203: U3.4 36.24,109.06 35.18,110.12 R17.2
N17430874: length 1.4
  TOP w0.203: R15.1 30.65,111.76 C29.1
N17430974: length 1.9
  TOP w0.203: C30.1 140.82,56.1
N17430995: length 46.6
  TOP w0.508: R19.2 144.35,64.57 143.48,65.44 121.79,65.44 116.33,59.98 116.33,50.35 118.01,48.67 120.69,48.67 FB7.1
N17431217: length 5.1
  TOP w0.203: U5.1 146.29,57.65 146.59,57.35 146.59,56.39 146.29,56.1 C30.2
N17431234: length 0.9
  TOP w0.203: R19.1 145.35,62.74 R20.2
N17431430: length 5.5
  TOP w0.203: R24.2 147.39,64.32 R22.1 147.39,60.74 146.84,60.19 U5.3
N17431436: length 5.3
  TOP w0.203: U5.6 139.79,60.19 139.16,60.81 139.16,62.61 C44.1 140.91,63.42 R23.2
N17431442: length 5.4
  TOP w0.203: 143.36,62.73 143.36,62.34 142.92,61.89 141.2,61.89 140.76,61.46 U5.5 ; 143.36,62.73 143.37,62.72 R20.1 ; 143.36,62.73 R26.2
N17431605: length 1.3
  TOP w0.203: R23.1 142,64.39 C45.1
N17445345: length 1.6
  TOP w0.254: C43.1 R21.2
N17445910: length 2
  TOP w0.203: C1.1 140.72,66.72
N17445924: length 27.3
  TOP w0.508: 118.68,73.79 119.68,74.79 137.1,74.79 138.71,76.4 143.6,76.4 144.1,75.89 R3.2
N17446104: length 5.2
  TOP w0.203: C1.2 146.34,66.72 146.67,67.04 146.67,68.01 146.33,68.35 U2.1
N17446121: length 1
  TOP w0.203: R4.2 145.09,75.25 R3.1
N17446263: length 5.3
  TOP w0.203: U2.6 139.88,70.89 139.25,71.52 139.25,74.12 C12.1 140.41,74.34 R5.2
N17446269: length 5.3
  TOP w0.203: U2.5 140.9,72.16 141.59,72.85 142.76,72.85 143.04,73.13 R8.2 144.08,74.27 R4.1
N17446309: length 2.2
  TOP w0.203: U2.4 146.11,72.48 R7.2
N17446353: length 1.4
  TOP w0.203: C13.1 141.59,75.29 R5.1
N17457092: length 1.8
  TOP w0.127: U8.28 102.67,30.82 102.66,30.84 R40.2
N17460494: length 6.3
  TOP w0.127: U17.31 129.03,86.6 129.4,86.24 129.4,82.93 TP7.1
N17467708: length 2.7
  TOP w0.127: U6.3 100.25,12.67 R30.2
N17467712: length 4.9
  TOP w0.127: U6.5 105.02,13.62 105.57,13.07 106.51,13.07 R31.1 107.09,12.5 C46.2 108.96,12.5 R27.2
N17467744: length 1.9
  TOP w0.127: U6.4 104.7,12.67 105.76,11.61 C57.1
N17473177: length 140.4
  TOP w0.127: v1(115.46,103.69) 115.23,103.46 115.23,102.87 114.5,102.14 113.66,102.14 C85.2
  L3 w0.127: v1(33.93,41.26) 34.16,41.49 34.16,41.91 44.36,52.11 55.85,52.11 57.17,50.78 86.72,50.78 95.92,59.98 106.4,59.98 108.36,61.94 108.36,104.55 109.49,105.68 114.11,105.68 115.23,104.56 115.23,103.92 v1(115.46,103.69)
  BOTTOM w0.127: J2.47 34.05,40.38 34.16,40.48 34.16,41.04 v1(33.93,41.26)
N17473180: length 140.4
  TOP w0.127: v1(114.7,103.69) 114.93,103.46 114.93,103 114.37,102.44 113.79,102.44 C86.2
  L3 w0.127: v1(34.69,41.26) 34.46,41.49 34.46,41.79 38.64,45.96 38.82,45.96 38.83,45.95 39.01,45.95 39.19,46.13 39.19,46.31 39.18,46.32 39.18,46.5 39.36,46.68 39.54,46.68 39.55,46.67 39.73,46.67 39.91,46.85 39.91,47.03 39.9,47.04 39.9,47.22 40.08,47.4 40.26,47.4 40.27,47.39 40.45,47.39 40.63,47.57 40.63,47.75 40.62,47.76 40.62,47.94 40.8,48.12 40.98,48.12 40.99,48.11 41.17,48.11 41.35,48.29 41.35,48.47 41.34,48.48 41.34,48.66 41.52,48.84 41.69,48.84 41.71,48.83 41.88,48.83 42.06,49.01 42.06,49.19 42.05,49.2 42.05,49.38 42.23,49.56 42.41,49.56 42.42,49.55 42.6,49.55 42.78,49.73 42.78,49.91 42.77,49.92 42.77,50.1 44.48,51.81 55.72,51.81 57.05,50.48 86.85,50.48 96.05,59.68 106.52,59.68 108.66,61.81 108.66,104.42 109.61,105.37 113.98,105.37 114.93,104.43 114.93,103.92 v1(114.7,103.69)
  BOTTOM w0.127: J2.49 34.55,40.4 34.46,40.5 34.46,41.04 v1(34.69,41.26)
N17481320: length 2.7
  BOTTOM w0.127: Q1.1 25.2,32.37 24.76,31.94 R56.1 24.75,31.87 R55.2
N17491651: length 29.9
  TOP w0.203: C175.2 18.14,13.41 40.32,13.41 40.95,14.04 40.95,16.34 43.11,18.5 U13.12
N17491658: length 31.7
  TOP w0.203: U13.13 43.51,18.5 43.49,18.48 43.49,18.41 41.37,16.28 41.37,13.89 40.51,13.03 18.57,13.03 17.49,11.95 C176.2
N17491664: length 15.1
  TOP w0.203: C177.2 43.52,11.92 44.99,13.4 44.99,17.58 45.51,18.1 U13.18
N17491670: length 16.7
  TOP w0.203: C178.2 36.64,10.86 37.26,11.48 43.66,11.48 45.37,13.19 45.37,17.42 45.89,17.94 45.89,19.46 U13.19
N17491675: length 8.1
  TOP w0.203: U13.24 47.91,18.73 47.89,18.71 47.89,17.78 49.1,16.58 49.1,12.58 49.29,12.38 C186.2
N17491677: length 7.6
  TOP w0.203: U13.25 48.31,18.5 48.3,18.49 48.3,18.17 48.31,18.16 48.31,17.91 49.5,16.72 49.5,12.89 C179.2
N17491684: length 24.7
  TOP w0.203: U13.30 50.31,18.58 54.56,14.32 54.56,12.21 56.82,9.95 68.12,9.95 68.69,10.52 C180.2
N17491690: length 24.2
  TOP w0.203: U13.31 50.71,18.78 54.96,14.53 54.96,12.38 56.99,10.35 67.97,10.35 C187.2
N17491701: length 6.6
  TOP w0.127: C188.2 38.72,15.03 C181.1 38.72,16.49 39.82,17.6 41.14,17.6 41.91,18.37 U13.9
N17491710: length 6.4
  TOP w0.127: U13.10 42.31,18.41 41.24,17.35 39.97,17.35 39.62,16.99 C181.2 39.62,16.01 C189.2
N17491714: length 5.2
  TOP w0.127: C182.2 42.74,16.02 C183.1 42.77,16.4 44.31,17.94 U13.15
N17491717: length 4.9
  TOP w0.127: U13.16 44.67,19.44 44.67,17.92 43.67,16.91 C183.2 43.69,16.01 C184.2
N17491723: length 4.5
  TOP w0.127: C190.2 46.67,16.06 C185.1 U13.21
N17491731: length 4.7
  TOP w0.127: U13.22 47.11,16.59 C185.2 47.63,16.07 C192.2
N17491737: length 5.2
  TOP w0.203: U13.27 49.13,19.46 49.13,19.32 49.14,19.3 49.14,18.39 50.81,16.72 50.81,16.26 C194.1 50.66,16.11 C193.2
N17491742: length 5.3
  TOP w0.203: U13.28 49.52,19.46 49.52,18.55 51.33,16.74 51.33,16.39 C194.2 51.61,16.11 C195.2
N17491772: length 4.5
  TOP w0.203: R105.2 37.2,37.1 38.79,37.1 39.51,36.38 U13.94
N17491776: length 5.6
  TOP w0.127: R108.2 57.05,25.86 56.08,25.86 R109.2 54.97,25.82 U13.45
N17491778: length 5.5
  TOP w0.127: R111.2 57.13,26.15 55.99,26.15 R110.2 55.06,26.22 U13.46
N17491878: length 3
  TOP w0.203: FB18.2 32.29,32.71 C191.1 32.29,34.55 Y2.4
N17491881: length 2.5
  TOP w0.203: R103.1 C196.1 33.94,35.41 Y2.1
N17521884: length 10.1
  TOP w0.127: 18.15,94.21 v1(18.14,94.21) ; 18.15,94.21 R116.1 ; 18.15,94.21 R113.1 ; D20.2 v1(23.54,88.15)
  BOTTOM w0.127: v1(18.14,94.21) 18.14,93.55 v1(23.54,88.15)
N17521978: length 2.5
  TOP w0.127: R115.2 23.7,94.89 C243.1 22.64,94.75 Q8.1
N17522055: length 1.5
  TOP w0.127: R118.1 D21.2
N17523462: length 2.9
  TOP w0.127: Q10.1 23.74,98.35 R120.1 21.76,98.35 Q11.3
N17523491: length 2.7
  TOP w0.127: Q11.1 18.56,98.53 18.19,98.15 R122.2 R121.1
N17524535: length 1.2
  TOP w0.508: D19.2 115.31,38.88 R100.2
N17524546: length 1.2
  TOP w0.508: R100.1 115.32,41.03 Q6.3
N17524572: length 2.7
  TOP w0.127: Q6.1 111.78,41.99 R102.2 R104.1
N17534566: length 3.6
  TOP w0.203: R11.2 2.35,101.12 C25.1 2.43,100.15 U4.3
N17543240: length 3.3
  TOP w0.559: U15.23 93.37,129.94 93.4,129.92 C256.2 94.35,128.95 F2.2
N17543343: length 2.8
  TOP w0.127: Q12.1 93.77,146.08 94.16,146.46 R136.1 95.89,146.46 R135.2
N17556572: length 2.5
  TOP w0.508: U18.1 v1(140.16,99.68)
  BOTTOM w0.508: C285.1 v1(140.16,99.68)
N17556623: length 2.5
  TOP w0.508: U18.4 v1(143.97,99.68)
  BOTTOM w0.508: C286.1 v1(143.97,99.68)
N17556674: length 2.5
  TOP w0.508: U18.7 v1(147.79,99.68)
  BOTTOM w0.508: C287.1 v1(147.79,99.68)
N17556725: length 2.5
  TOP w0.508: U18.10 v1(151.6,99.68)
  BOTTOM w0.508: C288.1 v1(151.6,99.68)
N17556884: length 14.6
  BOTTOM w0.508: C290.1 137.07,114.29 R197.2 R196.2 R195.2 R194.2
N17570124: length 1
  TOP w0.127: R229.2 R228.1
N17570191: length 1
  TOP w0.127: R231.2 R230.1
N17583651: length 1.6
  TOP w0.254: R268.1 41.26,120.72 41.26,120.36 C343.2
N17583654: length 1.6
  TOP w0.254: C344.2 41.81,120.35 41.81,120.71 R269.1
N17587612: length 3.7
  BOTTOM w0.127: R277.2 72.89,31.5 73.36,31.98 73.36,32.02 73.38,32.04 Q17.1 72.21,32.58 71.78,33.02 Q21.3
N17587654: length 2.5
  BOTTOM w0.127: Q21.1 68.46,32.61 68.45,32.63 R285.1 67.87,32.88 67.78,32.97 67.78,33.16 67.8,33.18 R281.2
N17590009: length 4.5
  BOTTOM w0.127: R291.2 83.51,23.91 83.04,23.45 Q26.3 82.51,23.45 81.54,24.42 Q23.1
N17590020: length 3.6
  BOTTOM w0.127: Q28.3 70.21,28.43 Q24.1 70.13,30.3 R292.2
N17590031: length 3.8
  BOTTOM w0.127: R293.2 82.39,30.42 Q25.1 81.63,29.36 82.6,28.39 Q29.3
N17590042: length 4.3
  BOTTOM w0.127: R290.2 70.52,25.38 70.99,24.91 70.99,23.54 Q27.3 70.45,23.27 69.48,24.24 Q22.1
N17590162: length 2.5
  BOTTOM w0.127: Q26.1 86.76,24.4 R299.1 86.76,23.46 R294.2
N17590173: length 2.5
  BOTTOM w0.127: Q28.1 73.24,29.4 R300.1 74.71,29.33 R295.2
N17590184: length 2.4
  BOTTOM w0.127: R296.2 86.71,28.43 R301.1 86.69,29.34 Q29.1
N17590195: length 2.4
  BOTTOM w0.127: Q27.1 74.61,24.22 R298.1 74.62,23.28 R297.2
N17591786: length 2.5
  TOP w0.508: U16.1 v1(118.27,99.66)
  BOTTOM w0.508: C260.1 v1(118.27,99.66)
N17591846: length 2.5
  TOP w0.508: U16.4 v1(122.08,99.66)
  BOTTOM w0.508: C261.1 v1(122.08,99.66)
N17591906: length 2.5
  TOP w0.508: U16.7 v1(125.9,99.66)
  BOTTOM w0.508: C262.1 v1(125.9,99.66)
N17591973: length 2.5
  TOP w0.508: U16.10 v1(129.71,99.66)
  BOTTOM w0.508: C263.1 v1(129.71,99.66)
N17592186: length 14.9
  BOTTOM w0.508: R150.2 R151.2 R152.2 R153.2 114.84,114.26 C265.1
N17604176: length 2.3
  TOP w0.127: U25.14 R306.1
N17604199: length 2.3
  TOP w0.127: U25.13 R307.1
N17604219: length 3.8
  TOP w0.127: C345.1 77.88,18.6 78.57,17.91 80.67,17.91 U25.3
